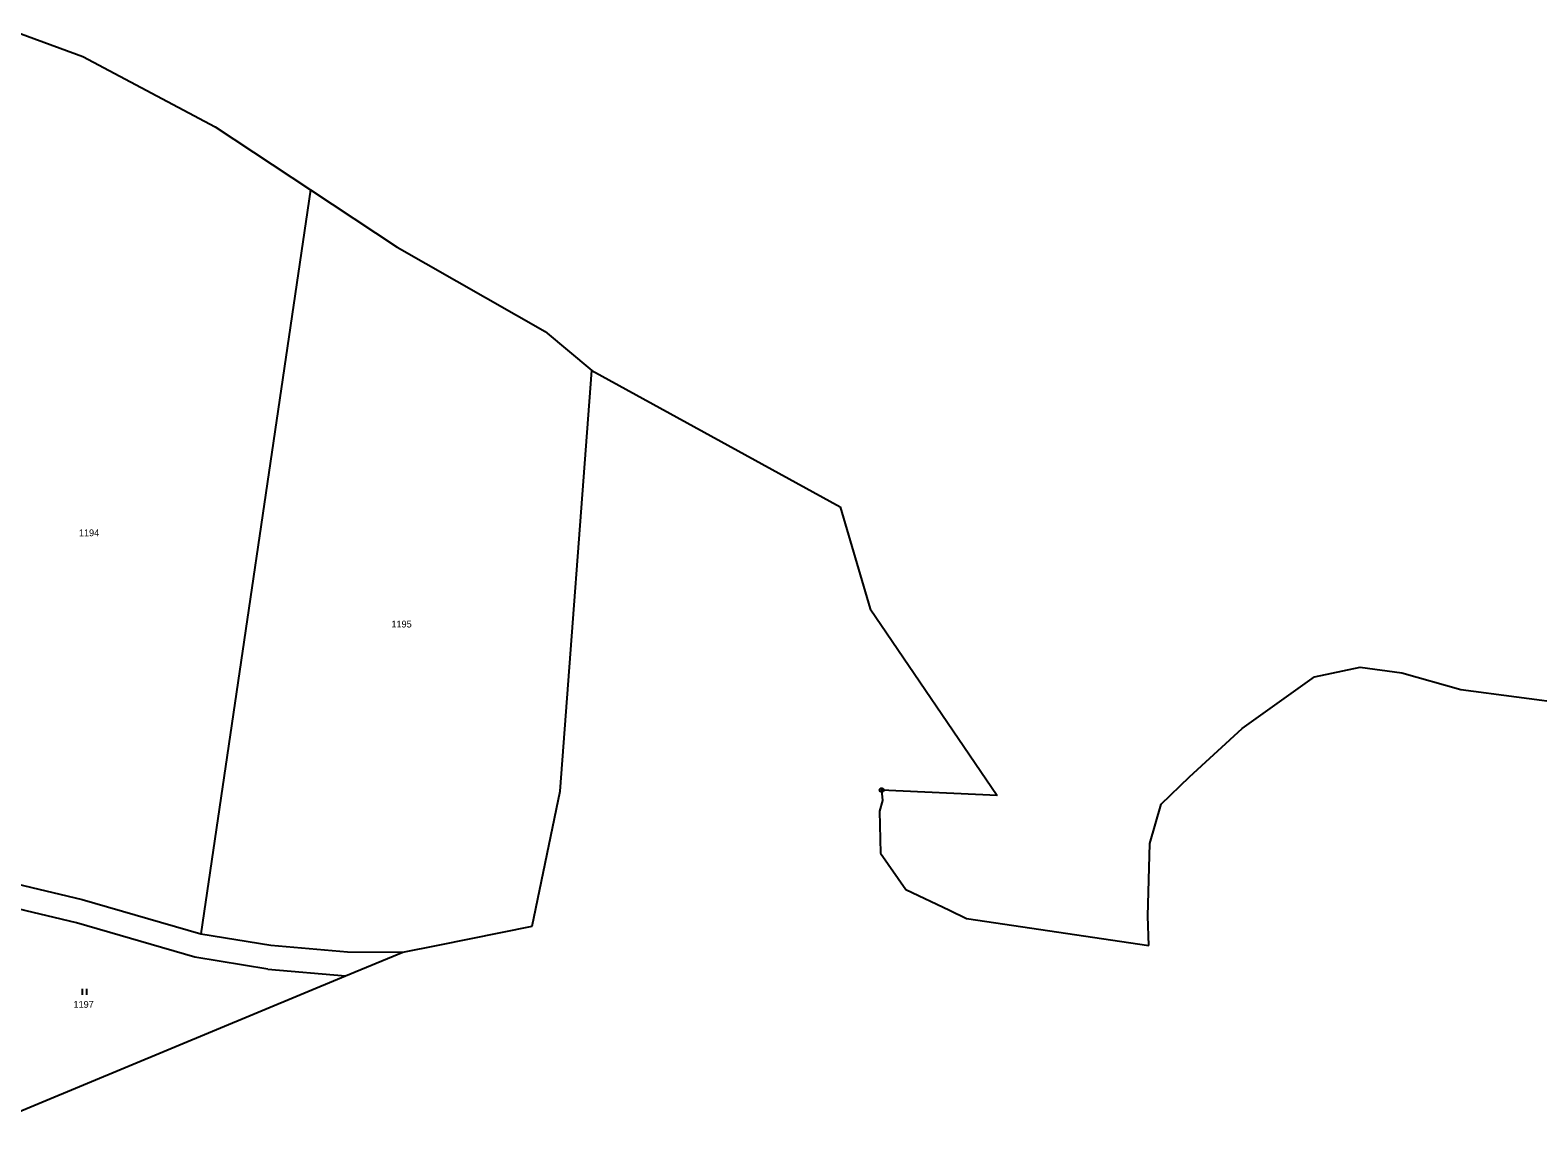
# Model space of a CAD drawing. Extents: x -796130 to -793145, y -1109506 to -1106267.
# Drawn here: x -793929.1 to -793552.6, y -1109235 to -1108961.6 of the extents above; entities that cross this region are included whole.
import ezdxf

# ---------------------------------------------------------------- set-up
doc = ezdxf.new("R2010")
doc.units = 0
for name, color, linetype in [('Vrstva 1', 7, 'Continuous'), ('Vrstva 14', 7, 'Continuous'), ('Vrstva 23', 7, 'Continuous'), ('Vrstva 28', 7, 'Continuous'), ('Vrstva 4', 7, 'Continuous')]:
    doc.layers.add(name, color=color, linetype=linetype)

msp = doc.modelspace()

# ---------------------------------------------------------------- linework, layer by layer
at = {"layer": 'Vrstva 1'}
for p, q in [((-793933.87, -1108961.6), (-793916, -1108968.2)), ((-793916, -1108968.2), (-793882.92, -1108985.74)), ((-793882.92, -1108985.74), (-793859.17, -1109001.47)), ((-793859.17, -1109001.47), (-793886.5, -1109187.31)), ((-793859.17, -1109001.47), (-793837.51, -1109015.82)), ((-793837.51, -1109015.82), (-793800.55, -1109036.85)), ((-793800.55, -1109036.85), (-793788.88, -1109046.64)), ((-793932.54, -1109174.79), (-793916.12, -1109178.76)), ((-793916.12, -1109178.76), (-793886.5, -1109187.31)), ((-793917.53, -1109184.59), (-793933.93, -1109180.62)), ((-793888.03, -1109193.14), (-793917.53, -1109184.59)), ((-793886.5, -1109187.31), (-793869.07, -1109190.18)), ((-793869.07, -1109190.18), (-793849.85, -1109191.82)), ((-793869.78, -1109196.14), (-793888.03, -1109193.14)), ((-793849.85, -1109191.82), (-793836.06, -1109191.86)), ((-793869.78, -1109196.14), (-793850.35, -1109197.8))]:
    msp.add_line(p, q, dxfattribs=at)
at = {"layer": 'Vrstva 23'}
for p, q in [((-793916.03, -1109202.54), (-793916.03, -1109201.04)), ((-793915.03, -1109201.04), (-793915.03, -1109202.54))]:
    msp.add_line(p, q, dxfattribs=at)
at = {"layer": 'Vrstva 28'}
for radius in [0.5, 0.01]:
    msp.add_circle((-793716.52, -1109151.43), radius, dxfattribs=at)
at = {"layer": 'Vrstva 4'}
for p, q in [((-793796.77, -1109151.72), (-793788.88, -1109046.64)), ((-793788.88, -1109046.64), (-793726.89, -1109080.65)), ((-793726.89, -1109080.65), (-793719.34, -1109106.17)), ((-793719.34, -1109106.17), (-793687.69, -1109152.76)), ((-793626.45, -1109136), (-793608.4, -1109123.1)), ((-793608.4, -1109123.1), (-793597, -1109120.7)), ((-793597, -1109120.7), (-793586.6, -1109122.15)), ((-793586.6, -1109122.15), (-793571.85, -1109126.33)), ((-793571.85, -1109126.33), (-793533.97, -1109131.3)), ((-793639.61, -1109148.11), (-793626.45, -1109136)), ((-793646.69, -1109154.96), (-793639.61, -1109148.11)), ((-793803.78, -1109185.38), (-793796.77, -1109151.72)), ((-793716.26, -1109153.99), (-793717.03, -1109156.72)), ((-793687.69, -1109152.76), (-793716.52, -1109151.43)), ((-793716.52, -1109151.43), (-793716.26, -1109153.99)), ((-793717.03, -1109156.72), (-793716.77, -1109167.14)), ((-793649.55, -1109164.79), (-793646.69, -1109154.96)), ((-793650.02, -1109182.94), (-793649.55, -1109164.79)), ((-793716.77, -1109167.14), (-793710.48, -1109176.24)), ((-793710.48, -1109176.24), (-793699.53, -1109181.44)), ((-793699.53, -1109181.44), (-793695.3, -1109183.45)), ((-793695.3, -1109183.45), (-793649.78, -1109190.2)), ((-793649.78, -1109190.2), (-793650.02, -1109182.94)), ((-793827.23, -1109190.12), (-793803.78, -1109185.38)), ((-793836.06, -1109191.86), (-793827.23, -1109190.12)), ((-793850.35, -1109197.8), (-793836.06, -1109191.86)), ((-793939.91, -1109235.03), (-793850.35, -1109197.8))]:
    msp.add_line(p, q, dxfattribs=at)

# ---------------------------------------------------------------- texts
at = {"layer": 'Vrstva 14'}
for s, p in [('1194', (-793916.959, -1109088.01)), ('1195', (-793838.919, -1109110.8)), ('1197', (-793918.31, -1109205.79))]:
    msp.add_text(s, height=1.7, dxfattribs=at).set_placement(p)

doc.saveas('drawing.dxf')
